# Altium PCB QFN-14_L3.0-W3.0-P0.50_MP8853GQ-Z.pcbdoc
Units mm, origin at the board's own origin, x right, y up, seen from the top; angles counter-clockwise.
Board outline 16.3 x 16.3 mm, 2 copper layers (Top Layer, Bottom Layer), stack 0 mm thick; 1 components, 0 nets, 14 pads, 0 vias.
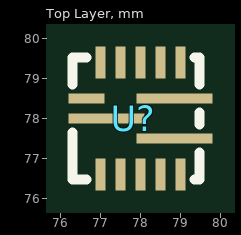
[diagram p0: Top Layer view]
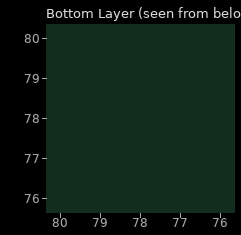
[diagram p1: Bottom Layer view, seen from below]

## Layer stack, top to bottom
Top Layer: signal copper (thickness not stored)
Bottom Layer: signal copper (thickness not stored)

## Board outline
86.15,69.85 69.85,69.85 69.85,86.15 86.15,86.15

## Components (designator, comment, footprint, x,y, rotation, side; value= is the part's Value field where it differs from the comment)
U? "" QFN-14_L3.0-W3.0-P0.50_MP8853GQ-Z 77.825,78 r0 top

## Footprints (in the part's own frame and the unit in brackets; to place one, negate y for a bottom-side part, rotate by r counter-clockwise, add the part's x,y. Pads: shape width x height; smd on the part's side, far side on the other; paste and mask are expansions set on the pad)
QFN-14_L3.0-W3.0-P0.50_MP8853GQ-Z [mm]
  rect 0.9x0.25 smd: 1(-1.175,0.5)
  rect 1.9x0.25 smd: 2(-0.675,0) 8(1.025,-0.5) 9(1.025,0.5)
  rect 0.25x0.8 smd: 3(-0.825,-1.4) 4(-0.325,-1.4) 5(0.175,-1.4) 6(0.675,-1.4) 7(1.175,-1.4) 10(1.175,1.4) 11(0.675,1.4) 12(0.175,1.4) 13(-0.325,1.4) 14(-0.825,1.4)
  silkscreen extent -1.52,-1.52 1.65,1.52

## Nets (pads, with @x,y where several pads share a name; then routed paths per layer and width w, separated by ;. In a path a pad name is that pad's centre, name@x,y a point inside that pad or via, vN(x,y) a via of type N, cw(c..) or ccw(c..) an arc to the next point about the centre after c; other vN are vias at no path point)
pads on no net: U?.1 U?.2 U?.3 U?.4 U?.5 U?.6 U?.7 U?.8 U?.9 U?.10 U?.11 U?.12 U?.13 U?.14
